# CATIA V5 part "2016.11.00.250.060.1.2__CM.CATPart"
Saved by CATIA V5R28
Part number: 2016.11.00.250.060.1.2__CM
Property "id_number": "2016.11.00.250.060.1.2"
Publications: "Absolute Axis System", "driver", "slider", "base", "cam diagram"
Bounding box of the stored display mesh (mm): x -60 to 230, y -180 to 180, z 0 to 330
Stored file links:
  N:\B2\Normteile\K\2016\11-14\025\cm\2016.11.00.250.060.1.2__CM.CATPart
  H:\CAD_Startmodelle\Tests\fill-in_PRT-SL_TEMPLATE.xlsx
  H:\CAD_Startmodelle\V5-R24\R24_TEMPLATE_PRT_FIBRO_CAM_TECNOLOGIES_INDEX.xlsx
  H:\z_Einordnen\170511__Anfrage_TK_HN\170511__CC01_TKHN.CATPart
  N:\B2\Normteile\K\2016\9xxx\2016.9024.1705.001\Entwurf_\170511__CC01_TKHN.CATPart
  N:\B2\Normteile\K\2016\9xxx\2016.9024.1707.006\Konstruktion\2016.9024.1707.006__HP__CUSTOMIZED_CAM_CM.CATPart
  N:\B2\Normteile\K\2016\9xxx\2016.9024.1707.005\Konstruktion\2016.9024.1707.005__HP__CUSTOMIZED_CAM_CM.CATPart
  N:\B2\Normteile\K\2016\9xxx\2016.9024.1707.008\Konstruktion\2016.9024.1707.008__HP__CUSTOMIZED_CAM_CM.CATPart
  N:\B2\Normteile\K\2016\9xxx\2016.9024.1707.009\Konstruktion\2016.9024.1707.009__HP__CUSTOMIZED_CAM_CM.CATPart
  N:\B2\Normteile\K\2016\9xxx\2016.9024.1707.010\Konstruktion\2016.9024.1707.010__HP__CUSTOMIZED_CAM_CM.CATPart
  N:\B2\Normteile\K\2016\9xxx\2016.9024.1708.002\Konstruktion\2016.9024.1708.002__HP__CUSTOMIZED_CAM_CM.CATPart
  N:\B2\Normteile\K\2016\9xxx\2016.9024.1802.001\Konstruktion\2016.9024.1802.001__HP__CUSTOMIZED_CAM_CM.CATPart
  N:\B2\Normteile\K\2016\9xxx\2016.9024.1802.002\Konstruktion\2016.9024.1802.002__HP__CUSTOMIZED_CAM_CM.CATPart
  N:\B2\Normteile\K\2016\9xxx\2016.9024.1811.003\Konstruktion\2016.9024.1811.003__HP__CUSTOMIZED_CAM_CM.CATPart
  N:\B2\Normteile\K\2016\9xxx\2016.9015.1811.001\Konstruktion\am\2016.9015.1811.001__AM__FCC_HV_DMC_0125-00.CATPart
  N:\B2\Normteile\K\2016\9xxx\2016.9024.1811.009\Konstruktion\2016.9024.1811.009__HP__CUSTOMIZED_CAM_CM.CATPart
  N:\B2\Normteile\K\2016\9xxx\2016.9024.1911.002\Konstruktion\am\2016.9024.1911.002__AM__CUSTOMIZED_CAM_CM.CATPart
  N:\B2\Normteile\K\2016\9xxx\2016.9024.2002.006\Konstruktion\2016.9024.2002.006__AM.CATPart
  N:\B2\Normteile\K\2016\9xxx\2016.9024.2004.001\Konstruktion\2016.9024.2004.001__AM__FCC_HV_CAEC_0260-45.CATPart
  N:\B2\Normteile\K\2016\9xxx\2016.9024.2006.002\Konstruktion\2016.9024.2006.002__AM__FCC_HV_CAEC_0260-40.CATPart
  N:\B2\Normteile\K\2016\9xxx\2016.9024.2006.005\Konstruktion\am\2016.9024.2006.005__AM__CFCC_HV_AEPC_0080-65.CATPart
  N:\B2\Normteile\K\2016\9xxx\2016.9024.2006.004\Konstruktion\am\2016.9024.2006.004__AM__CFCC_HV_AEC_0210-35.CATPart
  N:\B2\Normteile\K\2016\9xxx\2016.9026.2006.001\Konstruktion\am\2016.9026.2006.001__AM__FCC_LV_CAEC_0180-40.CATPart
  N:\B2\Normteile\K\2016\9xxx\2016.9015.2007.001\Konstruktion\am\2016.9015.2007.001__AM__FCC_HV_CDMPC_0090-00.CATPart
  N:\B2\Normteile\K\2016\9xxx\2016.9024.2005.001\Konstruktion\am\2016.9024.2005.001__AM__CFCC_HV_AEPC_1400-70.CATPart
  N:\B2\Normteile\K\2016\9xxx\2016.9024.2007.004\Konstruktion\am\2016.9024.2007.004__AM__CFCC_HV_AEC_1250-80.CATPart
  N:\B2\Normteile\K\2016\11-14\005\2016.11.00.052.040.1.02__AS__DIE_MOUNT_CAM__W52_A0_S40.CATProduct
  N:\B2\Normteile\K\2016\11-14\015\2016.11.00.150.060.1.02__AS__DIE_MOUNT_CAM__W150_A0_S60.CATProduct
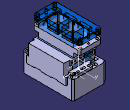
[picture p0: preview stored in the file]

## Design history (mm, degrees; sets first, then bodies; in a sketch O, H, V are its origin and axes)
Parameters
  group "process_parameters"
    modeltype = ""
    stocklist = ""
    id_number = "2016.11.00.250.060.1.2"
    id_number_rough_part = ""
    revision_index = ""
    revision_date = ""
    revision_description = ""
    category = ""
    material = ""
    manufacturing_information = ""
    standard = ""
  group "release_parameters_startmodel"
    sm_revision_index = "2016_00" {design table}
    sm_revision_date = "20.08.2016" {design table}
    sm_revision_name = "Meyer" {design table}
    sm_revision_description = "new part template FIBRO cam tecnologies" {design table}
AxisSystem1: origin (0, 0, 0), X (1, 0, 0), Y (0, 1, 0), Z (0, 0, 1)
Set1 "reference elements"
  Sketch1 "cam diagram" on ZX plane of AxisSystem1, origin (0, 0, 0), H (-1, 0, 0), V (0, 0, 1)
    line L1 (0, 0) -> (60, 0)
    line L2 (60, 0) -> (0, 60)
    point P2 (0, 60)
    line L3 (0, 60) -> (0, 0)
    length L1 = 60
    angle H L2 = 45
    horizontal: L1 H
    coincidence: P2 V
    vertical: L3 V
Body1 "finished_part" (main body)
  Body2 "rough_part"
  Add1 "rough_part": tool Body2
  Body3 "milling operations"
  Remove1 "milling operations": tool Body3
  Body4 "drilling operations"
  Remove2 "drilling operations": tool Body4
Body5 "driver"
  Solid1: solid without history
Body6 "slider"
  Solid2: solid without history
Body7 "base"
  Solid3: solid without history
Body8 "opened position"
  Body9 "slider"
    Body10 "slider"
      Solid4: linked copy from another document
    Assemble1: tool Body10
    Translate1: FirstPoint vertex [element of Sketch1 | element of Sketch1], SecondPoint vertex [element of Sketch1 | element of Sketch1], ToTransfor Assemble1
  Assemble2: tool Body9
  Body11 "driver"
    Body12 "driver"
      Solid5: linked copy from another document
    Assemble3: tool Body12
    Translate2: FirstPoint vertex [element of Sketch1 | element of Sketch1], SecondPoint vertex [element of Sketch1 | element of Sketch1], ToTransfor Assemble3
  Assemble4: tool Body11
